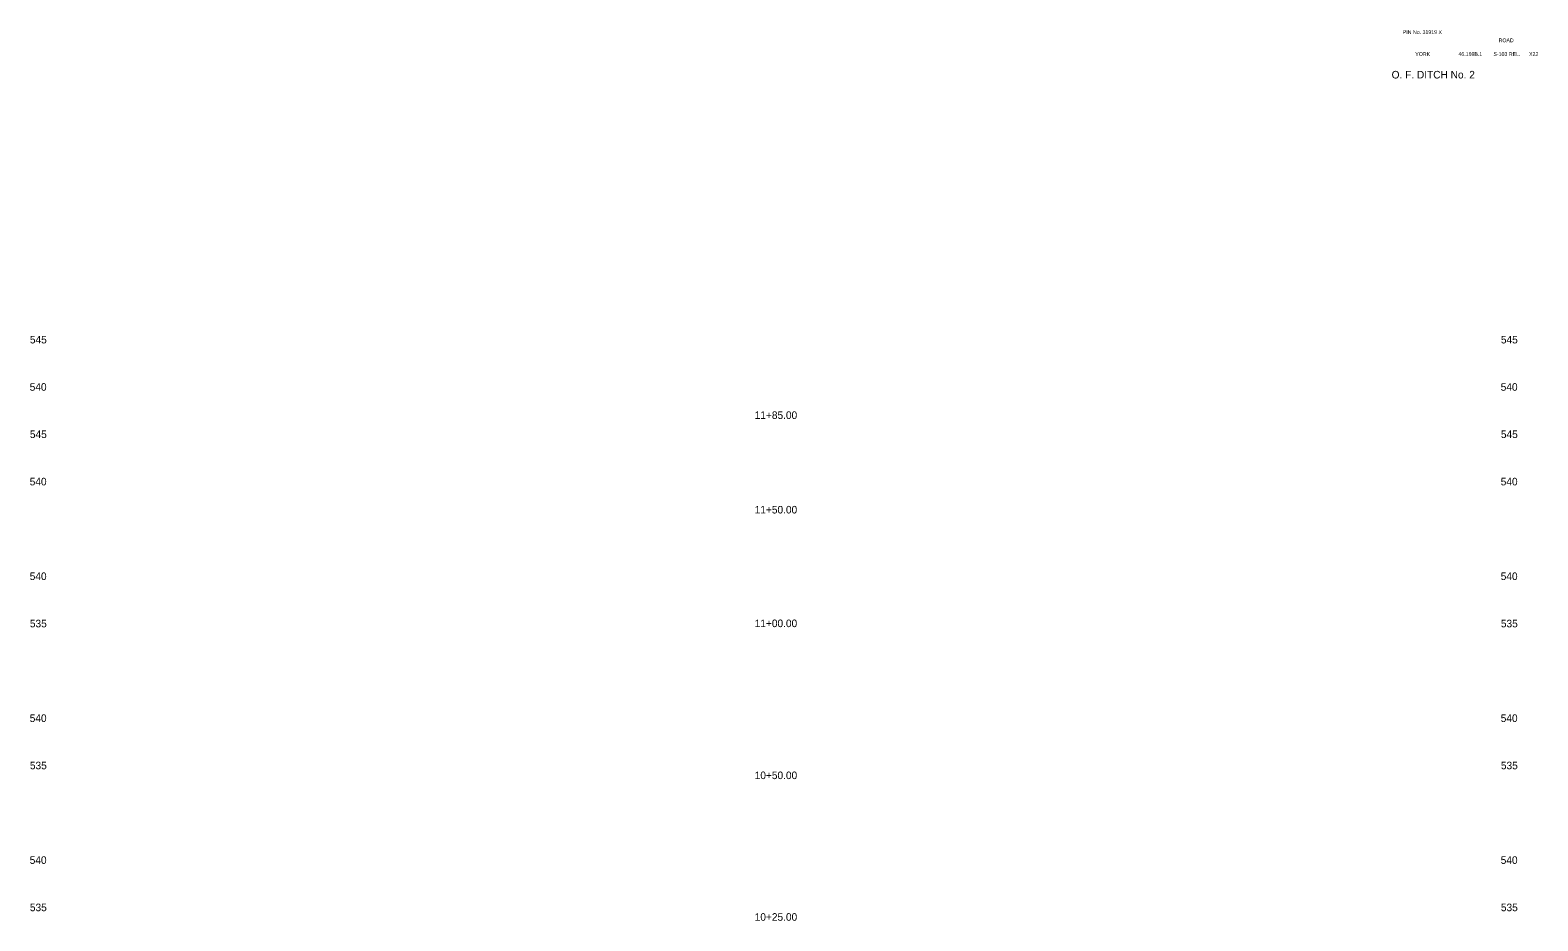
# Model space of a CAD drawing. Extents: x 1001 to 1161, y 1009 to 1103.
import ezdxf

# ---------------------------------------------------------------- set-up
doc = ezdxf.new("R2010")
doc.units = 0
for name, color, linetype in [('RD_SHT_TX', 7, 'Continuous'), ('RD_XS_TX_Elev_EX', 7, 'Continuous'), ('RD_XS_TX_Station', 7, 'Continuous')]:
    doc.layers.add(name, color=color, linetype=linetype)

msp = doc.modelspace()

# ---------------------------------------------------------------- texts
at = {"layer": 'RD_SHT_TX'}
for s, height, p in [('PIN No. 31919 X', 0.4, (1146.28, 1102.8)), ('ROAD', 0.4, (1156.41, 1101.93)), ('YORK', 0.4, (1147.6, 1100.48)), ('46.169B.1', 0.4, (1152.16, 1100.48)), ('S-103 REL.', 0.4, (1155.86, 1100.48)), ('X22', 0.4, (1159.63, 1100.48)), ('O. F. DITCH No. 2', 0.8, (1145.1, 1098.1))]:
    msp.add_text(s, height=height, dxfattribs=at).set_placement(p)
at = {"layer": 'RD_XS_TX_Elev_EX'}
for s, p in [('545', (1001.15, 1070.1)), ('545', (1156.65, 1070.1)), ('540', (1001.13, 1065.1)), ('540', (1156.63, 1065.1)), ('545', (1001.15, 1060.1)), ('545', (1156.65, 1060.1)), ('540', (1001.13, 1055.1)), ('540', (1156.63, 1055.1)), ('540', (1001.13, 1045.1)), ('540', (1156.63, 1045.1)), ('535', (1001.15, 1040.1)), ('535', (1156.65, 1040.1)), ('540', (1001.13, 1030.1)), ('540', (1156.63, 1030.1)), ('535', (1001.15, 1025.1)), ('535', (1156.65, 1025.1)), ('540', (1001.13, 1015.1)), ('540', (1156.63, 1015.1)), ('535', (1001.15, 1010.1)), ('535', (1156.65, 1010.1))]:
    msp.add_text(s, height=0.8, dxfattribs=at).set_placement(p)
at = {"layer": 'RD_XS_TX_Station'}
for s, p in [('11+85.00', (1077.77, 1062.12)), ('11+50.00', (1077.77, 1052.13)), ('11+00.00', (1077.77, 1040.12)), ('10+50.00', (1077.77, 1024.06)), ('10+25.00', (1077.77, 1009.09))]:
    msp.add_text(s, height=0.8, dxfattribs=at).set_placement(p)

doc.saveas('drawing.dxf')
